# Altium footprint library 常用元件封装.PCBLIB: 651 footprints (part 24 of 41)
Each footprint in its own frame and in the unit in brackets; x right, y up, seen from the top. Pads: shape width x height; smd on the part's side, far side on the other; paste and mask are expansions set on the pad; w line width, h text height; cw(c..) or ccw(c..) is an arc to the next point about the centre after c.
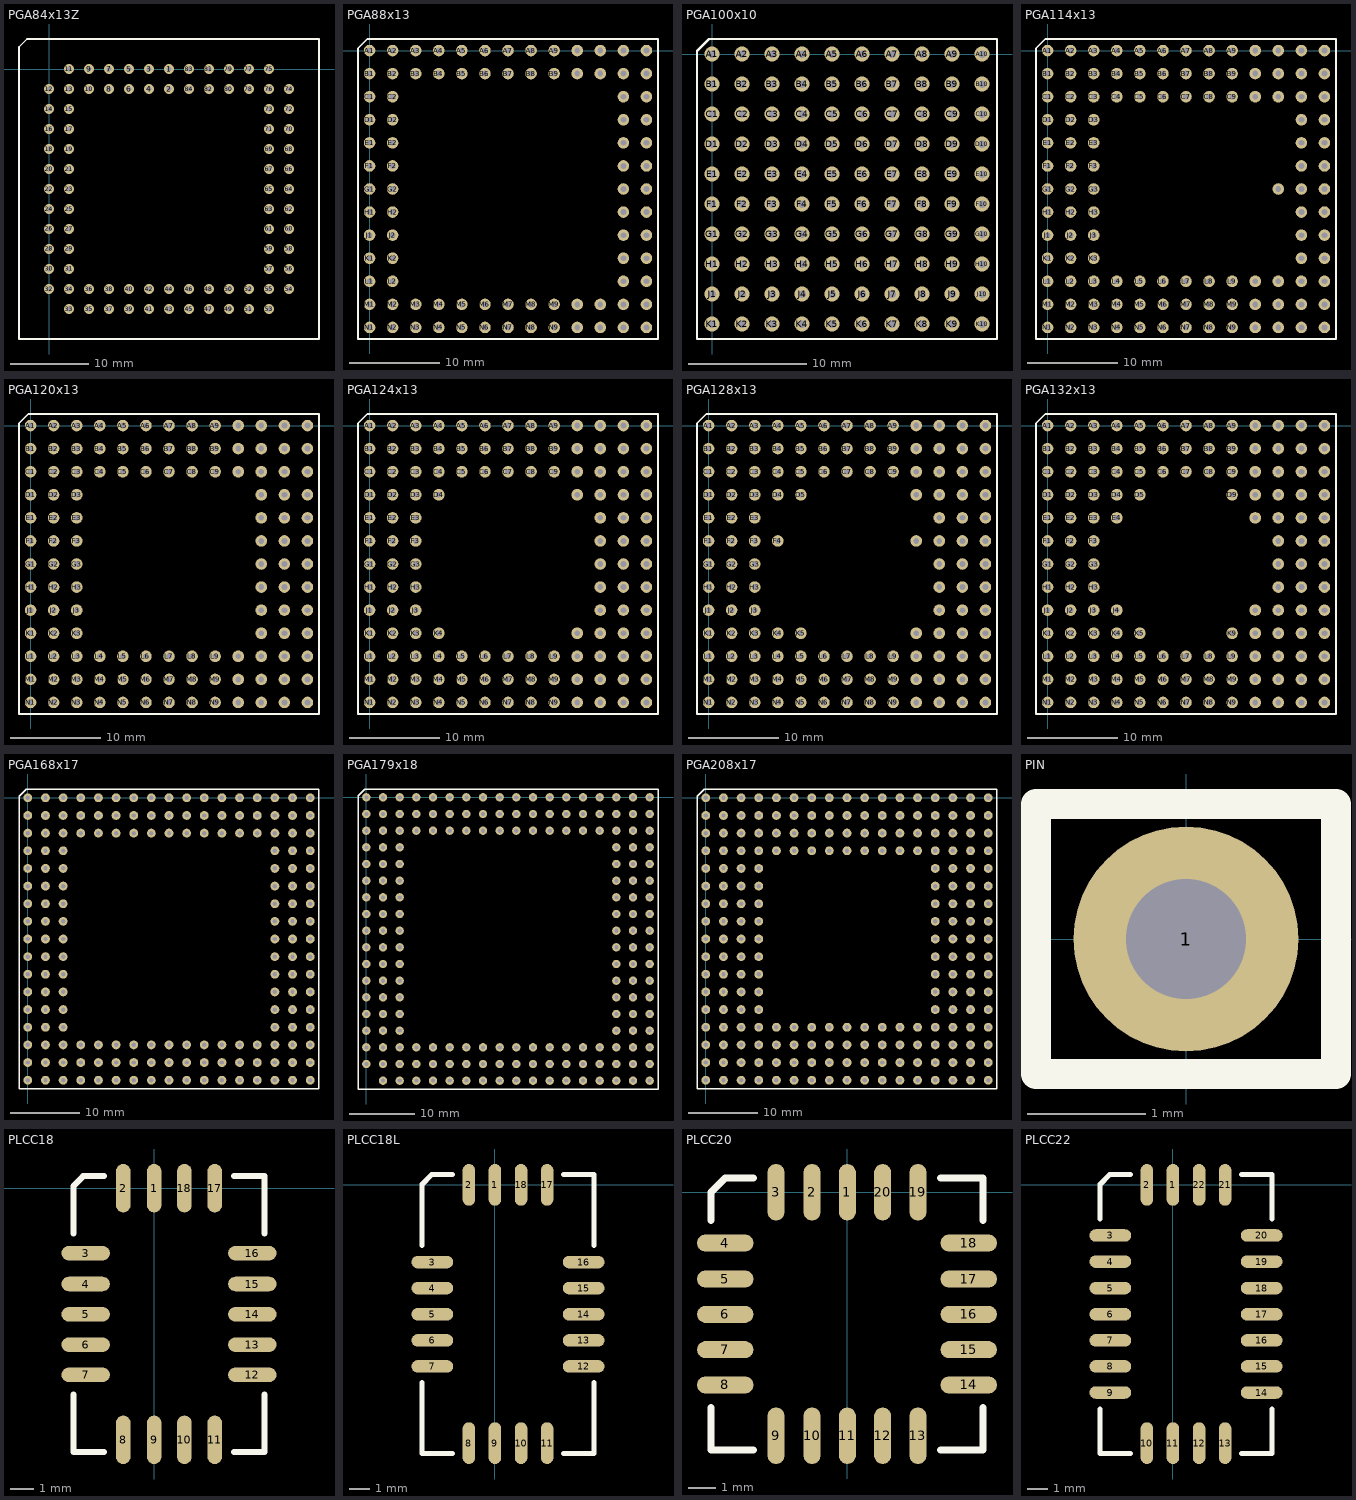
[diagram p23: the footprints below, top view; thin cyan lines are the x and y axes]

## PGA84x13Z [mil]
pads (84):
  round 50 hole 25: 1(600,0) 2(600,-100) 3(500,0) 4(500,-100) 5(400,0) 6(400,-100) 7(300,0) 8(300,-100) 9(200,0) 10(200,-100) 11(100,0) 12(0,-100) 13(100,-100) 14(0,-200) 15(100,-200) 16(0,-300) 17(100,-300) 18(0,-400) 19(100,-400) 20(0,-500) 21(100,-500) 22(0,-600) 23(100,-600) 24(0,-700) 25(100,-700) 26(0,-800) 27(100,-800) 28(0,-900) 29(100,-900) 30(0,-1000) 31(100,-1000) 32(0,-1100) 33(100,-1200) 34(100,-1100) 35(200,-1200) 36(200,-1100) 37(300,-1200) 38(300,-1100) 39(400,-1200) 40(400,-1100) 41(500,-1200) 42(500,-1100) 43(600,-1200) 44(600,-1100) 45(700,-1200) 46(700,-1100) 47(800,-1200) 48(800,-1100) 49(900,-1200) 50(900,-1100) 51(1000,-1200) 52(1000,-1100) 53(1100,-1200) 54(1200,-1100) 55(1100,-1100) 56(1200,-1000) 57(1100,-1000) 58(1200,-900) 59(1100,-900) 60(1200,-800) 61(1100,-800) 62(1200,-700) 63(1100,-700) 64(1200,-600) 65(1100,-600) 66(1200,-500) 67(1100,-500) 68(1200,-400) 69(1100,-400) 70(1200,-300) 71(1100,-300) 72(1200,-200) 73(1100,-200) 74(1200,-100) 75(1100,0) 76(1100,-100) 77(1000,0) 78(1000,-100) 79(900,0) 80(900,-100) 81(800,0) 82(800,-100) 83(700,0) 84(700,-100)
TopOverlay:
  lines w8: -150,-1350 1350,-1350 1350,150 -110,150 -150,110 -150,-1350

## PGA88x13 [mil]
pads (88):
  round 50 hole 25: A1(0,0) A2(100,0) A3(200,0) A4(300,0) A5(400,0) A6(500,0) A7(600,0) A8(700,0) A9(800,0) A10(900,0) A11(1000,0) A12(1100,0) A13(1200,0) B1(0,-100) B2(100,-100) B3(200,-100) B4(300,-100) B5(400,-100) B6(500,-100) B7(600,-100) B8(700,-100) B9(800,-100) B10(900,-100) B11(1000,-100) B12(1100,-100) B13(1200,-100) C1(0,-200) C2(100,-200) C12(1100,-200) C13(1200,-200) D1(0,-300) D2(100,-300) D12(1100,-300) D13(1200,-300) E1(0,-400) E2(100,-400) E12(1100,-400) E13(1200,-400) F1(0,-500) F2(100,-500) F12(1100,-500) F13(1200,-500) G1(0,-600) G2(100,-600) G12(1100,-600) G13(1200,-600) H1(0,-700) H2(100,-700) H12(1100,-700) H13(1200,-700) J1(0,-800) J2(100,-800) J12(1100,-800) J13(1200,-800) K1(0,-900) K2(100,-900) K12(1100,-900) K13(1200,-900) L1(0,-1000) L2(100,-1000) L12(1100,-1000) L13(1200,-1000) M1(0,-1100) M2(100,-1100) M3(200,-1100) M4(300,-1100) M5(400,-1100) M6(500,-1100) M7(600,-1100) M8(700,-1100) M9(800,-1100) M10(900,-1100) M11(1000,-1100) M12(1100,-1100) M13(1200,-1100) N1(0,-1200) N2(100,-1200) N3(200,-1200) N4(300,-1200) N5(400,-1200) N6(500,-1200) N7(600,-1200) N8(700,-1200) N9(800,-1200) N10(900,-1200) N11(1000,-1200) N12(1100,-1200) N13(1200,-1200)
TopOverlay:
  lines w8: -50,-1250 -50,10 -10,50 1250,50 1250,-1250 -50,-1250

## PGA100x10 [mil]
pads (100):
  round 50 hole 25: A1(0,0) A2(100,0) A3(200,0) A4(300,0) A5(400,0) A6(500,0) A7(600,0) A8(700,0) A9(800,0) A10(900,0) B1(0,-100) B2(100,-100) B3(200,-100) B4(300,-100) B5(400,-100) B6(500,-100) B7(600,-100) B8(700,-100) B9(800,-100) B10(900,-100) C1(0,-200) C2(100,-200) C3(200,-200) C4(300,-200) C5(400,-200) C6(500,-200) C7(600,-200) C8(700,-200) C9(800,-200) C10(900,-200) D1(0,-300) D2(100,-300) D3(200,-300) D4(300,-300) D5(400,-300) D6(500,-300) D7(600,-300) D8(700,-300) D9(800,-300) D10(900,-300) E1(0,-400) E2(100,-400) E3(200,-400) E4(300,-400) E5(400,-400) E6(500,-400) E7(600,-400) E8(700,-400) E9(800,-400) E10(900,-400) F1(0,-500) F2(100,-500) F3(200,-500) F4(300,-500) F5(400,-500) F6(500,-500) F7(600,-500) F8(700,-500) F9(800,-500) F10(900,-500) G1(0,-600) G2(100,-600) G3(200,-600) G4(300,-600) G5(400,-600) G6(500,-600) G7(600,-600) G8(700,-600) G9(800,-600) G10(900,-600) H1(0,-700) H2(100,-700) H3(200,-700) H4(300,-700) H5(400,-700) H6(500,-700) H7(600,-700) H8(700,-700) H9(800,-700) H10(900,-700) J1(0,-800) J2(100,-800) J3(200,-800) J4(300,-800) J5(400,-800) J6(500,-800) J7(600,-800) J8(700,-800) J9(800,-800) J10(900,-800) K1(0,-900) K2(100,-900) K3(200,-900) K4(300,-900) K5(400,-900) K6(500,-900) K7(600,-900) K8(700,-900) K9(800,-900) K10(900,-900)
TopOverlay:
  lines w8: -50,-950 -50,10 -10,50 950,50 950,-950 -50,-950

## PGA114x13 [mil]
pads (114):
  round 50 hole 25: A1(0,0) A2(100,0) A3(200,0) A4(300,0) A5(400,0) A6(500,0) A7(600,0) A8(700,0) A9(800,0) A10(900,0) A11(1000,0) A12(1100,0) A13(1200,0) B1(0,-100) B2(100,-100) B3(200,-100) B4(300,-100) B5(400,-100) B6(500,-100) B7(600,-100) B8(700,-100) B9(800,-100) B10(900,-100) B11(1000,-100) B12(1100,-100) B13(1200,-100) C1(0,-200) C2(100,-200) C3(200,-200) C4(300,-200) C5(400,-200) C6(500,-200) C7(600,-200) C8(700,-200) C9(800,-200) C10(900,-200) C11(1000,-200) C12(1100,-200) C13(1200,-200) D1(0,-300) D2(100,-300) D3(200,-300) D12(1100,-300) D13(1200,-300) E1(0,-400) E2(100,-400) E3(200,-400) E12(1100,-400) E13(1200,-400) F1(0,-500) F2(100,-500) F3(200,-500) F12(1100,-500) F13(1200,-500) G1(0,-600) G2(100,-600) G3(200,-600) G11(1000,-600) G12(1100,-600) G13(1200,-600) H1(0,-700) H2(100,-700) H3(200,-700) H12(1100,-700) H13(1200,-700) J1(0,-800) J2(100,-800) J3(200,-800) J12(1100,-800) J13(1200,-800) K1(0,-900) K2(100,-900) K3(200,-900) K12(1100,-900) K13(1200,-900) L1(0,-1000) L2(100,-1000) L3(200,-1000) L4(300,-1000) L5(400,-1000) L6(500,-1000) L7(600,-1000) L8(700,-1000) L9(800,-1000) L10(900,-1000) L11(1000,-1000) L12(1100,-1000) L13(1200,-1000) M1(0,-1100) M2(100,-1100) M3(200,-1100) M4(300,-1100) M5(400,-1100) M6(500,-1100) M7(600,-1100) M8(700,-1100) M9(800,-1100) M10(900,-1100) M11(1000,-1100) M12(1100,-1100) M13(1200,-1100) N1(0,-1200) N2(100,-1200) N3(200,-1200) N4(300,-1200) N5(400,-1200) N6(500,-1200) N7(600,-1200) N8(700,-1200) N9(800,-1200) N10(900,-1200) N11(1000,-1200) N12(1100,-1200) N13(1200,-1200)
TopOverlay:
  lines w8: -50,-1250 -50,10 -10,50 1250,50 1250,-1250 -50,-1250

## PGA120x13 [mil]
pads (120):
  round 50 hole 25: A1(0,0) A2(100,0) A3(200,0) A4(300,0) A5(400,0) A6(500,0) A7(600,0) A8(700,0) A9(800,0) A10(900,0) A11(1000,0) A12(1100,0) A13(1200,0) B1(0,-100) B2(100,-100) B3(200,-100) B4(300,-100) B5(400,-100) B6(500,-100) B7(600,-100) B8(700,-100) B9(800,-100) B10(900,-100) B11(1000,-100) B12(1100,-100) B13(1200,-100) C1(0,-200) C2(100,-200) C3(200,-200) C4(300,-200) C5(400,-200) C6(500,-200) C7(600,-200) C8(700,-200) C9(800,-200) C10(900,-200) C11(1000,-200) C12(1100,-200) C13(1200,-200) D1(0,-300) D2(100,-300) D3(200,-300) D11(1000,-300) D12(1100,-300) D13(1200,-300) E1(0,-400) E2(100,-400) E3(200,-400) E11(1000,-400) E12(1100,-400) E13(1200,-400) F1(0,-500) F2(100,-500) F3(200,-500) F11(1000,-500) F12(1100,-500) F13(1200,-500) G1(0,-600) G2(100,-600) G3(200,-600) G11(1000,-600) G12(1100,-600) G13(1200,-600) H1(0,-700) H2(100,-700) H3(200,-700) H11(1000,-700) H12(1100,-700) H13(1200,-700) J1(0,-800) J2(100,-800) J3(200,-800) J11(1000,-800) J12(1100,-800) J13(1200,-800) K1(0,-900) K2(100,-900) K3(200,-900) K11(1000,-900) K12(1100,-900) K13(1200,-900) L1(0,-1000) L2(100,-1000) L3(200,-1000) L4(300,-1000) L5(400,-1000) L6(500,-1000) L7(600,-1000) L8(700,-1000) L9(800,-1000) L10(900,-1000) L11(1000,-1000) L12(1100,-1000) L13(1200,-1000) M1(0,-1100) M2(100,-1100) M3(200,-1100) M4(300,-1100) M5(400,-1100) M6(500,-1100) M7(600,-1100) M8(700,-1100) M9(800,-1100) M10(900,-1100) M11(1000,-1100) M12(1100,-1100) M13(1200,-1100) N1(0,-1200) N2(100,-1200) N3(200,-1200) N4(300,-1200) N5(400,-1200) N6(500,-1200) N7(600,-1200) N8(700,-1200) N9(800,-1200) N10(900,-1200) N11(1000,-1200) N12(1100,-1200) N13(1200,-1200)
TopOverlay:
  lines w8: -50,-1250 1250,-1250 1250,50 -10,50 -50,10 -50,-1250

## PGA124x13 [mil]
pads (124):
  round 50 hole 25: A1(0,0) A2(100,0) A3(200,0) A4(300,0) A5(400,0) A6(500,0) A7(600,0) A8(700,0) A9(800,0) A10(900,0) A11(1000,0) A12(1100,0) A13(1200,0) B1(0,-100) B2(100,-100) B3(200,-100) B4(300,-100) B5(400,-100) B6(500,-100) B7(600,-100) B8(700,-100) B9(800,-100) B10(900,-100) B11(1000,-100) B12(1100,-100) B13(1200,-100) C1(0,-200) C2(100,-200) C3(200,-200) C4(300,-200) C5(400,-200) C6(500,-200) C7(600,-200) C8(700,-200) C9(800,-200) C10(900,-200) C11(1000,-200) C12(1100,-200) C13(1200,-200) D1(0,-300) D2(100,-300) D3(200,-300) D4(300,-300) D10(900,-300) D11(1000,-300) D12(1100,-300) D13(1200,-300) E1(0,-400) E2(100,-400) E3(200,-400) E11(1000,-400) E12(1100,-400) E13(1200,-400) F1(0,-500) F2(100,-500) F3(200,-500) F11(1000,-500) F12(1100,-500) F13(1200,-500) G1(0,-600) G2(100,-600) G3(200,-600) G11(1000,-600) G12(1100,-600) G13(1200,-600) H1(0,-700) H2(100,-700) H3(200,-700) H11(1000,-700) H12(1100,-700) H13(1200,-700) J1(0,-800) J2(100,-800) J3(200,-800) J11(1000,-800) J12(1100,-800) J13(1200,-800) K1(0,-900) K2(100,-900) K3(200,-900) K4(300,-900) K10(900,-900) K11(1000,-900) K12(1100,-900) K13(1200,-900) L1(0,-1000) L2(100,-1000) L3(200,-1000) L4(300,-1000) L5(400,-1000) L6(500,-1000) L7(600,-1000) L8(700,-1000) L9(800,-1000) L10(900,-1000) L11(1000,-1000) L12(1100,-1000) L13(1200,-1000) M1(0,-1100) M2(100,-1100) M3(200,-1100) M4(300,-1100) M5(400,-1100) M6(500,-1100) M7(600,-1100) M8(700,-1100) M9(800,-1100) M10(900,-1100) M11(1000,-1100) M12(1100,-1100) M13(1200,-1100) N1(0,-1200) N2(100,-1200) N3(200,-1200) N4(300,-1200) N5(400,-1200) N6(500,-1200) N7(600,-1200) N8(700,-1200) N9(800,-1200) N10(900,-1200) N11(1000,-1200) N12(1100,-1200) N13(1200,-1200)
TopOverlay:
  lines w8: -50,-1250 1250,-1250 1250,50 -10,50 -50,10 -50,-1250

## PGA128x13 [mil]
pads (128):
  round 50 hole 25: A1(0,0) A2(100,0) A3(200,0) A4(300,0) A5(400,0) A6(500,0) A7(600,0) A8(700,0) A9(800,0) A10(900,0) A11(1000,0) A12(1100,0) A13(1200,0) B1(0,-100) B2(100,-100) B3(200,-100) B4(300,-100) B5(400,-100) B6(500,-100) B7(600,-100) B8(700,-100) B9(800,-100) B10(900,-100) B11(1000,-100) B12(1100,-100) B13(1200,-100) C1(0,-200) C2(100,-200) C3(200,-200) C4(300,-200) C5(400,-200) C6(500,-200) C7(600,-200) C8(700,-200) C9(800,-200) C10(900,-200) C11(1000,-200) C12(1100,-200) C13(1200,-200) D1(0,-300) D2(100,-300) D3(200,-300) D4(300,-300) D5(400,-300) D10(900,-300) D11(1000,-300) D12(1100,-300) D13(1200,-300) E1(0,-400) E2(100,-400) E3(200,-400) E11(1000,-400) E12(1100,-400) E13(1200,-400) F1(0,-500) F2(100,-500) F3(200,-500) F4(300,-500) F10(900,-500) F11(1000,-500) F12(1100,-500) F13(1200,-500) G1(0,-600) G2(100,-600) G3(200,-600) G11(1000,-600) G12(1100,-600) G13(1200,-600) H1(0,-700) H2(100,-700) H3(200,-700) H11(1000,-700) H12(1100,-700) H13(1200,-700) J1(0,-800) J2(100,-800) J3(200,-800) J11(1000,-800) J12(1100,-800) J13(1200,-800) K1(0,-900) K2(100,-900) K3(200,-900) K4(300,-900) K5(400,-900) K10(900,-900) K11(1000,-900) K12(1100,-900) K13(1200,-900) L1(0,-1000) L2(100,-1000) L3(200,-1000) L4(300,-1000) L5(400,-1000) L6(500,-1000) L7(600,-1000) L8(700,-1000) L9(800,-1000) L10(900,-1000) L11(1000,-1000) L12(1100,-1000) L13(1200,-1000) M1(0,-1100) M2(100,-1100) M3(200,-1100) M4(300,-1100) M5(400,-1100) M6(500,-1100) M7(600,-1100) M8(700,-1100) M9(800,-1100) M10(900,-1100) M11(1000,-1100) M12(1100,-1100) M13(1200,-1100) N1(0,-1200) N2(100,-1200) N3(200,-1200) N4(300,-1200) N5(400,-1200) N6(500,-1200) N7(600,-1200) N8(700,-1200) N9(800,-1200) N10(900,-1200) N11(1000,-1200) N12(1100,-1200) N13(1200,-1200)
TopOverlay:
  lines w8: -50,-1250 -50,10 -10,50 1250,50 1250,-1250 -50,-1250

## PGA132x13 [mil]
pads (132):
  round 50 hole 25: A1(0,0) A2(100,0) A3(200,0) A4(300,0) A5(400,0) A6(500,0) A7(600,0) A8(700,0) A9(800,0) A10(900,0) A11(1000,0) A12(1100,0) A13(1200,0) B1(0,-100) B2(100,-100) B3(200,-100) B4(300,-100) B5(400,-100) B6(500,-100) B7(600,-100) B8(700,-100) B9(800,-100) B10(900,-100) B11(1000,-100) B12(1100,-100) B13(1200,-100) C1(0,-200) C2(100,-200) C3(200,-200) C4(300,-200) C5(400,-200) C6(500,-200) C7(600,-200) C8(700,-200) C9(800,-200) C10(900,-200) C11(1000,-200) C12(1100,-200) C13(1200,-200) D1(0,-300) D2(100,-300) D3(200,-300) D4(300,-300) D5(400,-300) D9(800,-300) D10(900,-300) D11(1000,-300) D12(1100,-300) D13(1200,-300) E1(0,-400) E2(100,-400) E3(200,-400) E4(300,-400) E10(900,-400) E11(1000,-400) E12(1100,-400) E13(1200,-400) F1(0,-500) F2(100,-500) F3(200,-500) F11(1000,-500) F12(1100,-500) F13(1200,-500) G1(0,-600) G2(100,-600) G3(200,-600) G11(1000,-600) G12(1100,-600) G13(1200,-600) H1(0,-700) H2(100,-700) H3(200,-700) H11(1000,-700) H12(1100,-700) H13(1200,-700) J1(0,-800) J2(100,-800) J3(200,-800) J4(300,-800) J10(900,-800) J11(1000,-800) J12(1100,-800) J13(1200,-800) K1(0,-900) K2(100,-900) K3(200,-900) K4(300,-900) K5(400,-900) K9(800,-900) K10(900,-900) K11(1000,-900) K12(1100,-900) K13(1200,-900) L1(0,-1000) L2(100,-1000) L3(200,-1000) L4(300,-1000) L5(400,-1000) L6(500,-1000) L7(600,-1000) L8(700,-1000) L9(800,-1000) L10(900,-1000) L11(1000,-1000) L12(1100,-1000) L13(1200,-1000) M1(0,-1100) M2(100,-1100) M3(200,-1100) M4(300,-1100) M5(400,-1100) M6(500,-1100) M7(600,-1100) M8(700,-1100) M9(800,-1100) M10(900,-1100) M11(1000,-1100) M12(1100,-1100) M13(1200,-1100) N1(0,-1200) N2(100,-1200) N3(200,-1200) N4(300,-1200) N5(400,-1200) N6(500,-1200) N7(600,-1200) N8(700,-1200) N9(800,-1200) N10(900,-1200) N11(1000,-1200) N12(1100,-1200) N13(1200,-1200)
TopOverlay:
  lines w8: -50,-1250 -50,10 -10,50 1250,50 1250,-1250 -50,-1250

## PGA168x17 [mil]
pads (168):
  round 50 hole 25: A1(0,0) A2(100,0) A3(200,0) A4(300,0) A5(400,0) A6(500,0) A7(600,0) A8(700,0) A9(800,0) A10(900,0) A11(1000,0) A12(1100,0) A13(1200,0) A14(1300,0) A15(1400,0) A16(1500,0) A17(1600,0) B1(0,-100) B2(100,-100) B3(200,-100) B4(300,-100) B5(400,-100) B6(500,-100) B7(600,-100) B8(700,-100) B9(800,-100) B10(900,-100) B11(1000,-100) B12(1100,-100) B13(1200,-100) B14(1300,-100) B15(1400,-100) B16(1500,-100) B17(1600,-100) C1(0,-200) C2(100,-200) C3(200,-200) C4(300,-200) C5(400,-200) C6(500,-200) C7(600,-200) C8(700,-200) C9(800,-200) C10(900,-200) C11(1000,-200) C12(1100,-200) C13(1200,-200) C14(1300,-200) C15(1400,-200) C16(1500,-200) C17(1600,-200) D1(0,-300) D2(100,-300) D3(200,-300) D15(1400,-300) D16(1500,-300) D17(1600,-300) E1(0,-400) E2(100,-400) E3(200,-400) E15(1400,-400) E16(1500,-400) E17(1600,-400) F1(0,-500) F2(100,-500) F3(200,-500) F15(1400,-500) F16(1500,-500) F17(1600,-500) G1(0,-600) G2(100,-600) G3(200,-600) G15(1400,-600) G16(1500,-600) G17(1600,-600) H1(0,-700) H2(100,-700) H3(200,-700) H15(1400,-700) H16(1500,-700) H17(1600,-700) J1(0,-800) J2(100,-800) J3(200,-800) J15(1400,-800) J16(1500,-800) J17(1600,-800) K1(0,-900) K2(100,-900) K3(200,-900) K15(1400,-900) K16(1500,-900) K17(1600,-900) L1(0,-1000) L2(100,-1000) L3(200,-1000) L15(1400,-1000) L16(1500,-1000) L17(1600,-1000) M1(0,-1100) M2(100,-1100) M3(200,-1100) M15(1400,-1100) M16(1500,-1100) M17(1600,-1100) N1(0,-1200) N2(100,-1200) N3(200,-1200) N15(1400,-1200) N16(1500,-1200) N17(1600,-1200) P1(0,-1300) P2(100,-1300) P3(200,-1300) P15(1400,-1300) P16(1500,-1300) P17(1600,-1300) Q1(0,-1400) Q2(100,-1400) Q3(200,-1400) Q4(300,-1400) Q5(400,-1400) Q6(500,-1400) Q7(600,-1400) Q8(700,-1400) Q9(800,-1400) Q10(900,-1400) Q11(1000,-1400) Q12(1100,-1400) Q13(1200,-1400) Q14(1300,-1400) Q15(1400,-1400) Q16(1500,-1400) Q17(1600,-1400) R1(0,-1500) R2(100,-1500) R3(200,-1500) R4(300,-1500) R5(400,-1500) R6(500,-1500) R7(600,-1500) R8(700,-1500) R9(800,-1500) R10(900,-1500) R11(1000,-1500) R12(1100,-1500) R13(1200,-1500) R14(1300,-1500) R15(1400,-1500) R16(1500,-1500) R17(1600,-1500) S1(0,-1600) S2(100,-1600) S3(200,-1600) S4(300,-1600) S5(400,-1600) S6(500,-1600) S7(600,-1600) S8(700,-1600) S9(800,-1600) S10(900,-1600) S11(1000,-1600) S12(1100,-1600) S13(1200,-1600) S14(1300,-1600) S15(1400,-1600) S16(1500,-1600) S17(1600,-1600)
TopOverlay:
  lines w8: -50,-1650 -50,10 -10,50 1650,50 1650,-1650 -50,-1650

## PGA179x18 [mil]
pads (179):
  round 50 hole 25: A1(0,0) A2(100,0) A3(200,0) A4(300,0) A5(400,0) A6(500,0) A7(600,0) A8(700,0) A9(800,0) A10(900,0) A11(1000,0) A12(1100,0) A13(1200,0) A14(1300,0) A15(1400,0) A16(1500,0) A17(1600,0) A18(1700,0) B1(0,-100) B2(100,-100) B3(200,-100) B4(300,-100) B5(400,-100) B6(500,-100) B7(600,-100) B8(700,-100) B9(800,-100) B10(900,-100) B11(1000,-100) B12(1100,-100) B13(1200,-100) B14(1300,-100) B15(1400,-100) B16(1500,-100) B17(1600,-100) B18(1700,-100) C1(0,-200) C2(100,-200) C3(200,-200) C4(300,-200) C5(400,-200) C6(500,-200) C7(600,-200) C8(700,-200) C9(800,-200) C10(900,-200) C11(1000,-200) C12(1100,-200) C13(1200,-200) C14(1300,-200) C15(1400,-200) C16(1500,-200) C17(1600,-200) C18(1700,-200) D1(0,-300) D2(100,-300) D3(200,-300) D16(1500,-300) D17(1600,-300) D18(1700,-300) E1(0,-400) E2(100,-400) E3(200,-400) E16(1500,-400) E17(1600,-400) E18(1700,-400) F1(0,-500) F2(100,-500) F3(200,-500) F16(1500,-500) F17(1600,-500) F18(1700,-500) G1(0,-600) G2(100,-600) G3(200,-600) G16(1500,-600) G17(1600,-600) G18(1700,-600) H1(0,-700) H2(100,-700) H3(200,-700) H16(1500,-700) H17(1600,-700) H18(1700,-700) J1(0,-800) J2(100,-800) J3(200,-800) J16(1500,-800) J17(1600,-800) J18(1700,-800) K1(0,-900) K2(100,-900) K3(200,-900) K16(1500,-900) K17(1600,-900) K18(1700,-900) L1(0,-1000) L2(100,-1000) L3(200,-1000) L16(1500,-1000) L17(1600,-1000) L18(1700,-1000) M1(0,-1100) M2(100,-1100) M3(200,-1100) M16(1500,-1100) M17(1600,-1100) M18(1700,-1100) N1(0,-1200) N2(100,-1200) N3(200,-1200) N16(1500,-1200) N17(1600,-1200) N18(1700,-1200) P1(0,-1300) P2(100,-1300) P3(200,-1300) P16(1500,-1300) P17(1600,-1300) P18(1700,-1300) Q1(0,-1400) Q2(100,-1400) Q3(200,-1400) Q16(1500,-1400) Q17(1600,-1400) Q18(1700,-1400) R1(0,-1500) R2(100,-1500) R3(200,-1500) R4(300,-1500) R5(400,-1500) R6(500,-1500) R7(600,-1500) R8(700,-1500) R9(800,-1500) R10(900,-1500) R11(1000,-1500) R12(1100,-1500) R13(1200,-1500) R14(1300,-1500) R15(1400,-1500) R16(1500,-1500) R17(1600,-1500) R18(1700,-1500) S1(0,-1600) S2(100,-1600) S3(200,-1600) S4(300,-1600) S5(400,-1600) S6(500,-1600) S7(600,-1600) S8(700,-1600) S9(800,-1600) S10(900,-1600) S11(1000,-1600) S12(1100,-1600) S13(1200,-1600) S14(1300,-1600) S15(1400,-1600) S16(1500,-1600) S17(1600,-1600) S18(1700,-1600) T2(100,-1700) T3(200,-1700) T4(300,-1700) T5(400,-1700) T6(500,-1700) T7(600,-1700) T8(700,-1700) T9(800,-1700) T10(900,-1700) T11(1000,-1700) T12(1100,-1700) T13(1200,-1700) T14(1300,-1700) T15(1400,-1700) T16(1500,-1700) T17(1600,-1700) T18(1700,-1700)
TopOverlay:
  lines w8: -50,-1750 -50,10 -10,50 1750,50 1750,-1750 -50,-1750

## PGA208x17 [mil]
pads (208):
  round 50 hole 25: A1(0,0) A2(100,0) A3(200,0) A4(300,0) A5(400,0) A6(500,0) A7(600,0) A8(700,0) A9(800,0) A10(900,0) A11(1000,0) A12(1100,0) A13(1200,0) A14(1300,0) A15(1400,0) A16(1500,0) A17(1600,0) B1(0,-100) B2(100,-100) B3(200,-100) B4(300,-100) B5(400,-100) B6(500,-100) B7(600,-100) B8(700,-100) B9(800,-100) B10(900,-100) B11(1000,-100) B12(1100,-100) B13(1200,-100) B14(1300,-100) B15(1400,-100) B16(1500,-100) B17(1600,-100) C1(0,-200) C2(100,-200) C3(200,-200) C4(300,-200) C5(400,-200) C6(500,-200) C7(600,-200) C8(700,-200) C9(800,-200) C10(900,-200) C11(1000,-200) C12(1100,-200) C13(1200,-200) C14(1300,-200) C15(1400,-200) C16(1500,-200) C17(1600,-200) D1(0,-300) D2(100,-300) D3(200,-300) D4(300,-300) D5(400,-300) D6(500,-300) D7(600,-300) D8(700,-300) D9(800,-300) D10(900,-300) D11(1000,-300) D12(1100,-300) D13(1200,-300) D14(1300,-300) D15(1400,-300) D16(1500,-300) D17(1600,-300) E1(0,-400) E2(100,-400) E3(200,-400) E4(300,-400) E14(1300,-400) E15(1400,-400) E16(1500,-400) E17(1600,-400) F1(0,-500) F2(100,-500) F3(200,-500) F4(300,-500) F14(1300,-500) F15(1400,-500) F16(1500,-500) F17(1600,-500) G1(0,-600) G2(100,-600) G3(200,-600) G4(300,-600) G14(1300,-600) G15(1400,-600) G16(1500,-600) G17(1600,-600) H1(0,-700) H2(100,-700) H3(200,-700) H4(300,-700) H14(1300,-700) H15(1400,-700) H16(1500,-700) H17(1600,-700) J1(0,-800) J2(100,-800) J3(200,-800) J4(300,-800) J14(1300,-800) J15(1400,-800) J16(1500,-800) J17(1600,-800) K1(0,-900) K2(100,-900) K3(200,-900) K4(300,-900) K14(1300,-900) K15(1400,-900) K16(1500,-900) K17(1600,-900) L1(0,-1000) L2(100,-1000) L3(200,-1000) L4(300,-1000) L14(1300,-1000) L15(1400,-1000) L16(1500,-1000) L17(1600,-1000) M1(0,-1100) M2(100,-1100) M3(200,-1100) M4(300,-1100) M14(1300,-1100) M15(1400,-1100) M16(1500,-1100) M17(1600,-1100) N1(0,-1200) N2(100,-1200) N3(200,-1200) N4(300,-1200) N14(1300,-1200) N15(1400,-1200) N16(1500,-1200) N17(1600,-1200) P1(0,-1300) P2(100,-1300) P3(200,-1300) P4(300,-1300) P5(400,-1300) P6(500,-1300) P7(600,-1300) P8(700,-1300) P9(800,-1300) P10(900,-1300) P11(1000,-1300) P12(1100,-1300) P13(1200,-1300) P14(1300,-1300) P15(1400,-1300) P16(1500,-1300) P17(1600,-1300) Q1(0,-1400) Q2(100,-1400) Q3(200,-1400) Q4(300,-1400) Q5(400,-1400) Q6(500,-1400) Q7(600,-1400) Q8(700,-1400) Q9(800,-1400) Q10(900,-1400) Q11(1000,-1400) Q12(1100,-1400) Q13(1200,-1400) Q14(1300,-1400) Q15(1400,-1400) Q16(1500,-1400) Q17(1600,-1400) R1(0,-1500) R2(100,-1500) R3(200,-1500) R4(300,-1500) R5(400,-1500) R6(500,-1500) R7(600,-1500) R8(700,-1500) R9(800,-1500) R10(900,-1500) R11(1000,-1500) R12(1100,-1500) R13(1200,-1500) R14(1300,-1500) R15(1400,-1500) R16(1500,-1500) R17(1600,-1500) S1(0,-1600) S2(100,-1600) S3(200,-1600) S4(300,-1600) S5(400,-1600) S6(500,-1600) S7(600,-1600) S8(700,-1600) S9(800,-1600) S10(900,-1600) S11(1000,-1600) S12(1100,-1600) S13(1200,-1600) S14(1300,-1600) S15(1400,-1600) S16(1500,-1600) S17(1600,-1600)
TopOverlay:
  lines w8: -50,-1650 -50,10 -10,50 1650,50 1650,-1650 -50,-1650

## PIN [mil]
pads (1):
  round 75 hole 40: 1(0,0)
TopOverlay:
  lines w10: -50,-45 50,-45 50,45 -50,45 -50,-45

## PLCC18 [mil]
pads (18):
  oval 24x80 smd: 1(0,0) 2(-51,0) 8(-51,-415) 9(0,-415) 10(50,-415) 11(100,-415) 17(100,0) 18(50,0)
  oval 80x24 smd: 3(-113,-107) 4(-113,-158) 5(-113,-208) 6(-113,-258) 7(-113,-308) 12(162,-308) 13(162,-258) 14(162,-208) 15(162,-158) 16(162,-107)
TopOverlay:
  lines w10: -133,-340 -133,-435 -83,-435 ; -133,-75 -133,4 -117,20 -83,20 ; 132,-435 182,-435 182,-340 ; 132,20 182,20 182,-75

## PLCC18L [mil]
pads (18):
  oval 24x80 smd: 1(0,0) 2(-50,0) 8(-50,-495) 9(0,-495) 10(50,-495) 11(100,-495) 17(100,0) 18(50,0)
  oval 80x24 smd: 3(-120,-148) 4(-120,-198) 5(-120,-248) 6(-120,-298) 7(-120,-348) 12(170,-348) 13(170,-298) 14(170,-248) 15(170,-198) 16(170,-148)
TopOverlay:
  lines w10: -140,-379 -140,-515 -82,-515 ; -140,-116 -140,1 -121,20 -82,20 ; 132,-515 190,-515 190,-379 ; 132,20 190,20 190,-116

## PLCC20 [mil]
pads (20):
  oval 24x80 smd: 1(0,0) 2(-50,0) 3(-101,0) 9(-101,-345) 10(-50,-345) 11(0,-345) 12(50,-345) 13(100,-345) 19(100,0) 20(50,0)
  oval 80x24 smd: 4(-173,-72) 5(-173,-123) 6(-173,-173) 7(-173,-223) 8(-173,-273) 14(172,-273) 15(172,-223) 16(172,-173) 17(172,-123) 18(172,-72)
TopOverlay:
  lines w10: -193,-305 -193,-365 -133,-365 ; -193,-40 -193,0 -173,20 -133,20 ; 132,-365 192,-365 192,-305 ; 132,20 192,20 192,-40

## PLCC22 [mil]
pads (22):
  oval 24x80 smd: 1(0,0) 2(-50,0) 10(-50,-495) 11(0,-495) 12(50,-495) 13(100,-495) 21(100,0) 22(50,0)
  oval 80x24 smd: 3(-120,-97) 4(-120,-147) 5(-120,-198) 6(-120,-248) 7(-120,-298) 8(-120,-348) 9(-120,-398) 14(170,-398) 15(170,-348) 16(170,-298) 17(170,-248) 18(170,-198) 19(170,-147) 20(170,-97)
TopOverlay:
  lines w10: -140,-430 -140,-515 -82,-515 ; -140,-65 -140,1 -121,20 -82,20 ; 132,-515 190,-515 190,-430 ; 132,20 190,20 190,-65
